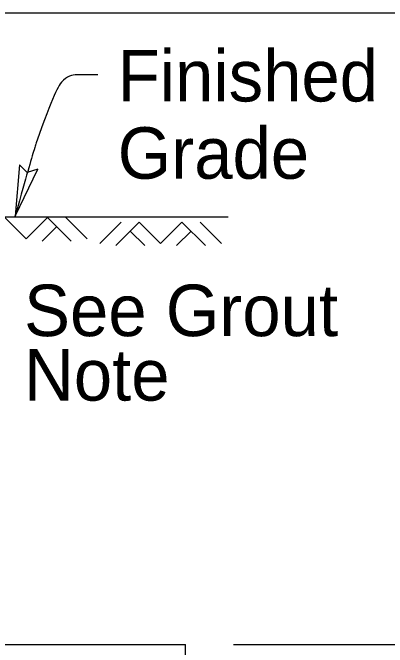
# Model space of a CAD drawing. Extents: x 0 to 2.83, y -0.03 to 1.83.
# Drawn here: x 1.5819 to 1.6766, y 1.0129 to 1.1732 of the extents above; entities that cross this region are included whole.
import ezdxf

# ---------------------------------------------------------------- set-up
doc = ezdxf.new("R2010")
doc.units = 0
for name, color, linetype in [('50', 7, 'Continuous'), ('54', 7, 'Continuous'), ('55', 7, 'Continuous'), ('57', 7, 'Continuous'), ('58', 7, 'Continuous')]:
    doc.layers.add(name, color=color, linetype=linetype)

msp = doc.modelspace()

# ---------------------------------------------------------------- linework, layer by layer
at = {"layer": '50'}
for p in [(1.3858653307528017, 1.013601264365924), (1.6255486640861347, 0.9429262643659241)]:
    msp.add_line(p, (1.6255486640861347, 1.013601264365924), dxfattribs=at)
at = {"layer": '54'}
msp.add_lwpolyline([(1.58250148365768, 1.1218135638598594), (1.5882273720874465, 1.1337147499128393), (1.5855380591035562, 1.1328881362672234), (1.583582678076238, 1.1348327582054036)], close=True, dxfattribs=at)
at = {"layer": '55'}
for p, q in [((1.5213304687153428, 1.1732433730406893), (1.7785573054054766, 1.1732433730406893)), ((1.63767639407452, 1.013601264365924), (1.856793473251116, 1.013601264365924))]:
    msp.add_line(p, q, dxfattribs=at)
for points in [[(1.6033821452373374, 1.1575212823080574), (1.60189797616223, 1.1575212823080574), (1.600413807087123, 1.1575212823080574), (1.5989296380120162, 1.1575212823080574), (1.594647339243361, 1.1575212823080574), (1.5920584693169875, 1.152314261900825), (1.5878085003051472, 1.140340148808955)], [(1.5878085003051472, 1.140340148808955), (1.5877237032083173, 1.1400670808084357), (1.587642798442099, 1.1397993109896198), (1.5875656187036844, 1.1395383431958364), (1.5858195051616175, 1.133634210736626), (1.5841265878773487, 1.127740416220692), (1.58250148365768, 1.1218135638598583)]]:
    msp.add_open_spline(points, degree=3, dxfattribs=at)
at = {"layer": '58'}
for p, q in [((1.528542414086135, 1.1216857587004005), (1.63631324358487, 1.1216857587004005)), ((1.5799362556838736, 1.1214982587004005), (1.5853237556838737, 1.1161107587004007)), ((1.5907112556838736, 1.1214982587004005), (1.5853237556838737, 1.1161107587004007)), ((1.5907112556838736, 1.1214982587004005), (1.5966612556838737, 1.1155482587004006)), ((1.5952987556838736, 1.1214982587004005), (1.6006862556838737, 1.1161107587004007)), ((1.6093112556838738, 1.1203295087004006), (1.6039237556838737, 1.1149420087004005)), ((1.6138987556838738, 1.1203295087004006), (1.6079487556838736, 1.1143795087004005)), ((1.6138987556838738, 1.1203295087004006), (1.6192862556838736, 1.1149420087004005)), ((1.6246737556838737, 1.1203295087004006), (1.6192862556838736, 1.1149420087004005)), ((1.6246737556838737, 1.1203295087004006), (1.6306237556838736, 1.1143795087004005)), ((1.6292612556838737, 1.1203295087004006), (1.6346487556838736, 1.1149420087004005)), ((1.5930362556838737, 1.1192295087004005), (1.5893487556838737, 1.1155482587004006)), ((1.6115737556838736, 1.1180607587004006), (1.6152612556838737, 1.1143795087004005)), ((1.6269987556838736, 1.1180607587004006), (1.6233112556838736, 1.1143795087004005))]:
    msp.add_line(p, q, dxfattribs=at)

# ---------------------------------------------------------------- texts
at = {"layer": '57'}
for s, p in [('Finished ', (1.6084331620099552, 1.1508077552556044)), ('Grade', (1.6084331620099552, 1.1312827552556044)), ('See Grout ', (1.5847783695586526, 1.0915201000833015)), ('Note', (1.5847783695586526, 1.0752236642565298))]:
    msp.add_text(s, height=0.013016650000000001, dxfattribs=at).set_placement(p)

doc.saveas('drawing.dxf')
